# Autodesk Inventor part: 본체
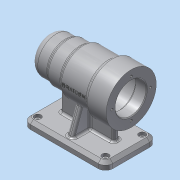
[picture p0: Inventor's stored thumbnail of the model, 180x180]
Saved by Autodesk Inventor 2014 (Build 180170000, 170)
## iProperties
Created: 2016-06
Part Number: 본체
Material: 알루미늄 6061
Document SubType Name: Modeling
Designer: dgall
Density: 2.71 g/cm^3
Appearance: 알루미늄 - 평지
Mass: 673.897 g
Surface Area: 647.223 cm^2
Volume: 248.67 cm^3
Author: dgall
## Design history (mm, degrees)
sketch "스케치1"
  geometry: L1 (-56, 0)-(56, 0); L2 (-56, 0)-(-56, 25); L3 (-56, 25)-(-31, 25); L4 (-31, 25)-(-31, 27); L5 (-31, 27)-(-11, 27); L6 (-11, 27)-(-11, 30); L7 (-11, 30)-(28, 30); L8 (28, 30)-(28, 34); L9 (28, 34)-(56, 34); L10 (56, 34)-(56, 0); 2 further points
  constraints: 20 end point, 6 parallel, 2 vertical, 1 coincident, 1 horizontal, 1 midpoint, 1 perpendicular
  dimensions: "d0" = 112 distance of L1.start L1.end; "d1" = 25 distance of L2.end L3.end; "d3" = 45 distance between parallel lines of L6 L2; "d4" = 84 distance between parallel lines of L8 L2; "d6" = 50 diameter of L3 L1; "d7" = 54 diameter of L5 L1; "d8" = 60 diameter of L7 L1; "d9" = 68 diameter of L9 L1
revolve "회전1" sketch "스케치1" stored, may be unused: angle "d10" = 90 deg
sketch "스케치2"
  geometry: L1 (-56, -25)-(-56, 25) reference; L2 (56, -34)-(56, 34) reference; L3 (-56, 0)-(56, 0); L4 (-50, 0)-(-50, 10.5); L5 (-50, 10.5)-(-47, 10.5); L6 (-47, 10.5)-(-47, 16); L7 (-47, 16)-(-43, 16); L8 (-43, 16)-(-43, 17.5); L9 (-43, 17.5)-(-25, 17.5); L10 (-25, 17.5)-(-25, 21); L11 (-25, 21)-(-13, 21); L12 (-13, 21)-(-13, 24); L13 (-13, 24)-(41, 24); L14 (41, 24)-(41, 21); L15 (41, 21)-(56, 21); 1 further point
  constraints: 26 end point, 6 parallel, 4 perpendicular, 2 midpoint, 2 point on line, 1 horizontal, 1 vertical
  dimensions: "d11" = 3 distance of L4.end L5.end; "d12" = 4 distance of L6.end L7.end; "d13" = 18 distance of L8.end L9.end; "d14" = 12 distance of L10.end L11.end; "d15" = 54 distance of L12.end L13.end; "d16" = 15 distance of L14.end L15.end; "d18" = 21 diameter of L5 L3; "d19" = 32 diameter of L7 L3; "d20" = 35 diameter of L9 L3; "d21" = 42 diameter of L11 L3; "d22" = 48 diameter of L13 L3; "d23" = 42 diameter of L15 L3
revolve "회전2" sketch "스케치2" stored, may be unused: angle "d24" = 90 deg
fillet "모깎기1" dims "d25" = 10
fillet "모깎기2" dims "d26" = 3
fillet "모깎기3" dims "d27" = 3
fillet "모깎기4" dims "d28" = 0.3
chamfer "모따기1" distance "d30" = 1; stored, may be unused: second distance "d31" = 2, angle "d32" = 45 deg
sketch "스케치3"
  geometry: C1 r 34 at (0, 0) reference; 1 further point
  constraints: 1 vertical alignment
  dimensions: "d33" = 26 distance of point (0, 26) C1.centre
hole "구멍1" sketch "스케치3" at (0, 26) diameter "d34" = 3.242; stored, may be unused: countersink angle "d38" = 90 deg, drill point angle "d40" = 118 deg; dims "d35" = 8, "d36" = 4, "d37" = 2, "d39" = 11
node "작업 평면1"
sketch "스케치4"
  geometry: L1 (47.5, -34)-(47.5, 34) reference; 2 further points
  constraints: 1 horizontal alignment, 1 other
  dimensions: "d44" = 48 distance from line of L1 point (-0.5, 0)
feature "엠보싱1" sketch "스케치4" dims "d45" = 0.5, "d46" = 0
node "작업 평면2"
sketch "스케치5"
  geometry: L1 (-56, 35)-(56, 35); L2 (56, 35)-(56, -35); L3 (56, -35)-(-56, -35); L4 (-56, -35)-(-56, 35); 3 further points
  constraints: 8 end point, 2 midpoint, 2 parallel, 1 horizontal, 1 horizontal alignment, 1 perpendicular, 1 vertical alignment
  dimensions: "d48" = 112 distance of L1.start L1.end; "d49" = 70 distance of L3.end L1.start
extrude "돌출1" join sketch "스케치5" distance "d50" = 10; taper "d51" = 0 deg
fillet "모깎기6" dims "d52" = 10
chamfer "모따기2" distance "d53" = 4; stored, may be unused: second distance "d54" = 2, angle "d55" = 45 deg
hole "구멍2" diameter "d58" = 5; stored, may be unused: countersink angle "d62" = 90 deg, drill point angle "d64" = 0 deg; dims "d56" = 10, "d57" = 10, "d59" = 8, "d60" = 9, "d61" = 4, "d63" = 11
sketch "스케치6"
  geometry: L1 (-15.509, -25.68)-(-28, -60); L2 (-35, -70)-(-35, -64) reference; L3 (-25, -70)-(-35, -70) reference; L4 (-29.5, -60)-(-20.5, -60) reference; L5 (-25, -60)-(25, -60) reference; L6 (0, -30)-(0, -60); L7 (15.509, -25.68)-(28, -60); L8 (-28, -60)-(28, -60); A1 r 30 centre (0, 0) between (-15.509, -25.68) and (0, -30) reference; A2 r 30 centre (0, 0) between (-15.509, -25.68) and (15.509, -25.68); 1 further point
  constraints: 8 end point, 6 point on circle, 2 point on line, 2 symmetric about line, 1 centre point, 1 collinear, 1 midpoint, 1 vertical
  dimensions: "d65" = 7 distance from line of L1.end L2; "d66" = 110 deg angle of L1 L3
extrude "돌출2" join sketch "스케치6" stored distance "d67" = 8; taper "d68" = 0 deg
sketch "스케치7"
  geometry: L1 (-36, 4)-(36, 4); L2 (36, 4)-(36, -4); L3 (36, -4)-(-36, -4); L4 (-36, -4)-(-36, 4); L5 (-56, 25)-(-56, -25) reference; 3 further points
  constraints: 8 end point, 2 midpoint, 2 parallel, 1 horizontal, 1 horizontal alignment, 1 perpendicular, 1 vertical alignment
  dimensions: "d69" = 8 distance of L3.end L1.start; "d70" = 20 distance between parallel lines of L4 L5
extrude "돌출3" join sketch "스케치7" stored distance "d71" = 8; taper "d72" = 0 deg
fillet "모깎기7" dims "d73" = 3
fillet "모깎기8" dims "d74" = 3
fillet "모깎기9" dims "d75" = 3
fillet "모깎기10" dims "d76" = 3
fillet "모깎기11" dims "d77" = 3
fillet "모깎기12" dims "d78" = 3
node "솔리드1"
pattern_circular "원형 패턴1" dims angle "d42" = 360 deg
mirror "대칭1"
mirror "대칭2"
